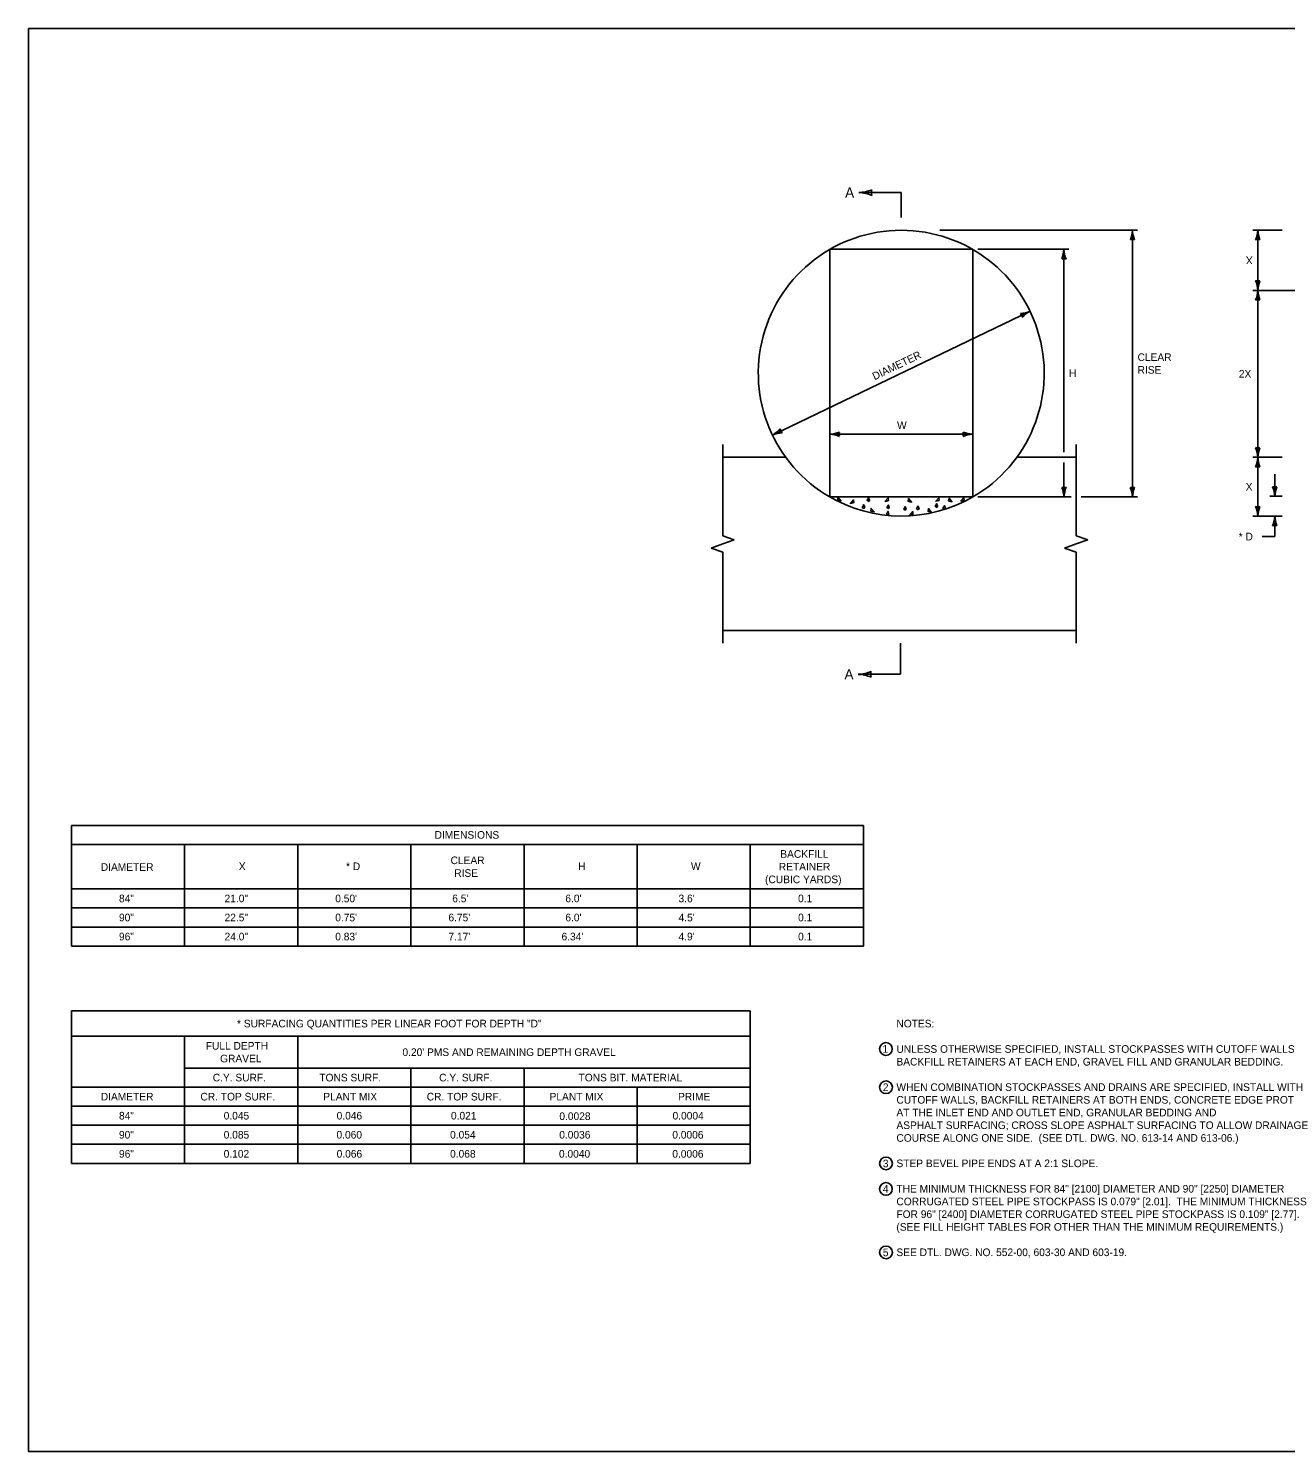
# Model space of a CAD drawing. Extents: x 49991.4 to 50021, y 49987.6 to 50011.4.
# Drawn here: x 49999.38 to 50009.28, y 49987.8 to 49999 of the extents above; entities that cross this region are included whole.
import ezdxf

# ---------------------------------------------------------------- set-up
doc = ezdxf.new("R2010")
doc.units = 0
for name, color, linetype in [('Level 1', 7, 'Continuous'), ('Level 2', 7, 'Continuous'), ('Level 3', 7, 'Continuous'), ('Level 4', 7, 'Continuous'), ('Level 6', 7, 'Continuous')]:
    doc.layers.add(name, color=color, linetype=linetype)

msp = doc.modelspace()

# ---------------------------------------------------------------- linework, layer by layer
at = {"layer": 'Level 1'}
for p, q in [((50004.848, 49995.624), (50005.344, 49995.624)), ((50007.162, 49995.624), (50007.63, 49995.624)), ((50005.691, 49995.312), (50006.816, 49995.312)), ((50004.848, 49994.261), (50007.63, 49994.261))]:
    msp.add_line(p, q, dxfattribs=at)
msp.add_lwpolyline([(49999.384, 49998.999), (50016.75, 49998.999), (50016.75, 49987.799), (49999.384, 49987.799)], close=True, dxfattribs=at)
for points in [[(50005.781, 49995.278), (50005.755, 49995.309), (50005.753, 49995.287), (50005.778, 49995.281)], [(50005.781, 49995.278), (50005.755, 49995.309), (50005.753, 49995.287), (50005.778, 49995.281)], [(50005.851, 49995.258), (50005.877, 49995.288), (50005.879, 49995.267), (50005.853, 49995.26)], [(50005.961, 49995.252), (50005.946, 49995.23), (50005.959, 49995.222), (50005.965, 49995.233), (50005.954, 49995.252)], [(50005.999, 49995.307), (50005.984, 49995.286), (50005.997, 49995.277), (50006.004, 49995.288), (50005.993, 49995.307)], [(50006.124, 49995.275), (50006.15, 49995.305), (50006.152, 49995.283), (50006.126, 49995.277)], [(50006.154, 49995.251), (50006.139, 49995.229), (50006.152, 49995.221), (50006.158, 49995.232), (50006.148, 49995.251)], [(50006.287, 49995.238), (50006.272, 49995.217), (50006.285, 49995.208), (50006.291, 49995.219), (50006.28, 49995.238)], [(50006.335, 49995.269), (50006.309, 49995.299), (50006.307, 49995.278), (50006.332, 49995.271)], [(50006.388, 49995.241), (50006.373, 49995.22), (50006.386, 49995.211), (50006.393, 49995.222), (50006.382, 49995.241)], [(50006.535, 49995.26), (50006.52, 49995.239), (50006.532, 49995.23), (50006.539, 49995.241), (50006.528, 49995.26)], [(50006.523, 49995.276), (50006.549, 49995.306), (50006.551, 49995.285), (50006.526, 49995.278)], [(50006.596, 49995.245), (50006.581, 49995.223), (50006.594, 49995.214), (50006.601, 49995.225), (50006.59, 49995.245)], [(50006.654, 49995.272), (50006.629, 49995.302), (50006.626, 49995.281), (50006.652, 49995.274)], [(50006.719, 49995.278), (50006.745, 49995.308), (50006.747, 49995.287), (50006.721, 49995.28)], [(50006.042, 49995.192), (50006.016, 49995.222), (50006.014, 49995.2), (50006.04, 49995.194)], [(50006.152, 49995.199), (50006.137, 49995.177), (50006.15, 49995.168), (50006.156, 49995.179), (50006.146, 49995.199)], [(50006.317, 49995.167), (50006.343, 49995.197), (50006.345, 49995.176), (50006.32, 49995.169)], [(50006.492, 49995.19), (50006.467, 49995.22), (50006.464, 49995.198), (50006.49, 49995.192)]]:
    msp.add_lwpolyline(points, dxfattribs=at)
for start, end in [(299.9973, 240.0046), (239.1121, 300.3985), (239.1121, 300.3985)]:
    msp.add_arc((50006.253, 49996.286), 1.125, start, end, dxfattribs=at)
at = {"layer": 'Level 2'}
for p, q in [((49999.721, 49992.727), (49999.721, 49991.777)), ((49999.721, 49992.727), (50005.956, 49992.727)), ((50005.956, 49992.727), (50005.956, 49991.777)), ((49999.721, 49992.577), (50005.956, 49992.577)), ((50000.612, 49992.577), (50000.612, 49991.777)), ((50001.503, 49992.577), (50001.503, 49991.777)), ((50002.393, 49992.577), (50002.393, 49991.777)), ((50003.284, 49992.577), (50003.284, 49991.777)), ((50004.175, 49992.577), (50004.175, 49991.777)), ((50005.065, 49992.577), (50005.065, 49991.777)), ((49999.721, 49992.227), (50005.956, 49992.227)), ((49999.721, 49992.077), (50005.956, 49992.077)), ((49999.721, 49991.927), (50005.956, 49991.927)), ((49999.721, 49991.777), (50005.956, 49991.777)), ((49999.721, 49991.267), (49999.721, 49990.067)), ((49999.721, 49991.267), (50005.065, 49991.267)), ((50005.065, 49991.267), (50005.065, 49990.067)), ((49999.721, 49991.067), (50005.065, 49991.067)), ((50000.612, 49991.067), (50000.612, 49990.067)), ((50001.503, 49991.067), (50001.503, 49990.067)), ((50000.612, 49990.817), (50005.065, 49990.817)), ((50002.393, 49990.817), (50002.393, 49990.067)), ((50003.284, 49990.817), (50003.284, 49990.067)), ((49999.719, 49990.667), (50005.065, 49990.667)), ((50004.175, 49990.667), (50004.175, 49990.067)), ((49999.721, 49990.517), (50005.065, 49990.517)), ((49999.721, 49990.367), (50005.065, 49990.367)), ((50003.284, 49990.382), (50003.284, 49990.167)), ((49999.721, 49990.217), (50005.065, 49990.217)), ((49999.721, 49990.067), (50005.065, 49990.067))]:
    msp.add_line(p, q, dxfattribs=at)
for centre in [(50006.132, 49990.967), (50006.133, 49990.666), (50006.133, 49990.066), (50006.132, 49989.866), (50006.133, 49989.366)]:
    msp.add_circle(centre, 0.05, dxfattribs=at)
at = {"layer": 'Level 3'}
for p, q in [((50008.113, 49997.411), (50006.556, 49997.411)), ((50008.073, 49997.411), (50008.073, 49995.312)), ((50009.251, 49997.411), (50009.019, 49997.411)), ((50009.059, 49997.411), (50009.059, 49996.938)), ((50006.856, 49997.261), (50007.573, 49997.261)), ((50007.533, 49997.261), (50007.533, 49995.664)), ((50010.527, 49996.938), (50009.019, 49996.938)), ((50009.059, 49996.938), (50009.059, 49995.624)), ((50005.239, 49995.799), (50007.267, 49996.773)), ((50005.691, 49995.806), (50006.816, 49995.806)), ((50007.533, 49995.312), (50007.533, 49995.584)), ((50009.251, 49995.624), (50009.019, 49995.624)), ((50009.059, 49995.624), (50009.059, 49995.161)), ((50009.193, 49995.49), (50009.193, 49995.317)), ((50006.856, 49995.312), (50007.59, 49995.312)), ((50007.67, 49995.312), (50008.113, 49995.312)), ((50009.153, 49995.317), (50009.251, 49995.317)), ((50009.251, 49995.161), (50009.019, 49995.161)), ((50009.193, 49995.161), (50009.193, 49995)), ((50009.094, 49995), (50009.193, 49995))]:
    msp.add_line(p, q, dxfattribs=at)
for centre, radius, start, end in [((50005.904, 49998.018), 0.311, 272.8273, 292.0772), ((50005.907, 49997.412), 0.296, 67.456, 87.6395), ((50006.09, 49997.708), 0.073, 162.1388, 197.8612), ((50007.851, 49997.42), 0.222, 337.456, 357.6395), ((50008.305, 49997.423), 0.233, 182.8273, 202.0772), ((50008.837, 49997.42), 0.222, 337.456, 357.6395), ((50009.292, 49997.423), 0.233, 182.8273, 202.0772), ((50007.311, 49997.27), 0.222, 337.456, 357.6395), ((50007.766, 49997.272), 0.233, 182.8273, 202.0772), ((50008.073, 49997.283), 0.0548, 72.1388, 107.8612), ((50009.059, 49997.283), 0.0548, 72.1388, 107.8612), ((50007.533, 49997.132), 0.0548, 72.1388, 107.8612), ((50009.059, 49997.066), 0.0548, 252.1388, 287.8612), ((50008.826, 49996.927), 0.233, 2.8273, 22.0772), ((50008.837, 49996.947), 0.222, 337.456, 357.6395), ((50009.281, 49996.929), 0.222, 157.456, 177.6395), ((50009.292, 49996.95), 0.233, 182.8273, 202.0772), ((50009.059, 49996.81), 0.0548, 72.1388, 107.8612), ((50007.179, 49996.978), 0.222, 273.1134, 293.2969), ((50007.152, 49996.718), 0.0548, 7.7962, 43.5185), ((50007.378, 49996.569), 0.233, 118.4847, 137.7345), ((50005.128, 49996.004), 0.233, 298.4847, 317.7345), ((50005.327, 49995.595), 0.222, 93.1134, 113.2969), ((50005.355, 49995.855), 0.0548, 187.7962, 223.5185), ((50005.679, 49996.038), 0.233, 272.8273, 292.0772), ((50005.682, 49995.583), 0.222, 67.456, 87.6395), ((50005.819, 49995.806), 0.0548, 162.1388, 197.8612), ((50006.825, 49996.028), 0.222, 247.456, 267.6395), ((50006.687, 49995.806), 0.0548, 342.1388, 17.8612), ((50006.827, 49995.573), 0.233, 92.8273, 112.0772), ((50009.059, 49995.752), 0.0548, 252.1388, 287.8612), ((50008.826, 49995.612), 0.233, 2.8273, 22.0772), ((50009.281, 49995.614), 0.222, 157.456, 177.6395), ((50008.837, 49995.633), 0.222, 337.456, 357.6395), ((50009.292, 49995.635), 0.233, 182.8273, 202.0772), ((50009.059, 49995.495), 0.0548, 72.1388, 107.8612), ((50007.533, 49995.44), 0.0548, 252.1388, 287.8612), ((50007.301, 49995.3), 0.233, 2.8273, 22.0772), ((50007.756, 49995.303), 0.222, 157.456, 177.6395), ((50008.073, 49995.44), 0.0548, 252.1388, 287.8612), ((50007.84, 49995.3), 0.233, 2.8273, 22.0772), ((50008.295, 49995.303), 0.222, 157.456, 177.6395), ((50009.193, 49995.445), 0.0548, 252.1388, 287.8612), ((50008.96, 49995.305), 0.233, 2.8273, 22.0772), ((50009.415, 49995.307), 0.222, 157.456, 177.6395), ((50009.059, 49995.289), 0.0548, 252.1388, 287.8612), ((50008.826, 49995.15), 0.233, 2.8273, 22.0772), ((50009.281, 49995.152), 0.222, 157.456, 177.6395), ((50008.971, 49995.17), 0.222, 337.456, 357.6395), ((50009.426, 49995.173), 0.233, 182.8273, 202.0772), ((50009.193, 49995.033), 0.0548, 72.1388, 107.8612), ((50005.899, 49994.226), 0.311, 272.8273, 292.0772), ((50005.902, 49993.62), 0.296, 67.456, 87.6395), ((50006.085, 49993.916), 0.073, 162.1388, 197.8612)]:
    msp.add_arc(centre, radius, start, end, dxfattribs=at)
at = {"layer": 'Level 4'}
for p, q in [((50005.691, 49995.312), (50005.691, 49997.261)), ((50005.691, 49997.261), (50006.816, 49997.261)), ((50006.816, 49995.312), (50006.816, 49997.261))]:
    msp.add_line(p, q, dxfattribs=at)
at = {"layer": 'Level 6'}
for p, q in [((50006.253, 49997.708), (50005.92, 49997.708)), ((50006.253, 49997.708), (50006.253, 49997.511)), ((50004.848, 49995.724), (50004.848, 49995.007)), ((50007.63, 49995.724), (50007.63, 49995.007)), ((50004.939, 49994.975), (50004.848, 49995.007)), ((50007.722, 49994.975), (50007.63, 49995.007)), ((50004.848, 49994.942), (50004.757, 49994.91)), ((50004.848, 49994.878), (50004.757, 49994.91)), ((50004.939, 49994.975), (50004.848, 49994.942)), ((50007.63, 49994.942), (50007.539, 49994.91)), ((50007.63, 49994.878), (50007.539, 49994.91)), ((50007.722, 49994.975), (50007.63, 49994.942)), ((50004.848, 49994.878), (50004.848, 49994.161)), ((50007.63, 49994.878), (50007.63, 49994.161)), ((50006.248, 49994.161), (50006.248, 49993.916)), ((50006.248, 49993.916), (50005.914, 49993.916))]:
    msp.add_line(p, q, dxfattribs=at)

# ---------------------------------------------------------------- texts
at = {"layer": 'Level 2'}
for s, height, p in [('A', 0.08, (50005.811, 49997.668)), ('CLEAR', 0.06, (50008.113, 49996.382)), ('H', 0.06, (50007.573, 49996.256)), ('RISE', 0.06, (50008.113, 49996.282)), ('2X', 0.06, (50008.91, 49996.251)), ('W', 0.06, (50006.22, 49995.846)), ('X', 0.06, (50008.964, 49995.362)), ('* D', 0.06, (50008.909, 49994.97)), ('A', 0.08, (50005.806, 49993.876)), ('DIMENSIONS', 0.06, (50002.58, 49992.622)), ('DIAMETER', 0.06, (49999.953, 49992.369)), ('X', 0.06, (50001.039, 49992.375)), ('* D', 0.06, (50001.883, 49992.375)), ('CLEAR', 0.06, (50002.706, 49992.422)), ('H', 0.06, (50003.71, 49992.375)), ('W', 0.06, (50004.598, 49992.375)), ('RETAINER', 0.06, (50005.289, 49992.372)), ('BACKFILL', 0.06, (50005.301, 49992.472)), ('RISE', 0.06, (50002.735, 49992.322)), ('(CUBIC YARDS)', 0.06, (50005.181, 49992.272)), ('84"', 0.06, (50000.096, 49992.122)), ('21.0"', 0.06, (50000.927, 49992.122)), ("0.50'", 0.06, (50001.798, 49992.122)), ("6.5'", 0.06, (50002.719, 49992.122)), ("6.0'", 0.06, (50003.609, 49992.122)), ("3.6'", 0.06, (50004.5, 49992.122)), ('0.1', 0.06, (50005.441, 49992.122)), ('90"', 0.06, (50000.096, 49991.972)), ('22.5"', 0.06, (50000.927, 49991.972)), ("0.75'", 0.06, (50001.798, 49991.972)), ("6.75'", 0.06, (50002.689, 49991.972)), ("6.0'", 0.06, (50003.609, 49991.972)), ("4.5'", 0.06, (50004.5, 49991.972)), ('0.1', 0.06, (50005.441, 49991.972)), ('96"', 0.06, (50000.096, 49991.822)), ('24.0"', 0.06, (50000.927, 49991.822)), ("0.83'", 0.06, (50001.798, 49991.822)), ("7.17'", 0.06, (50002.689, 49991.822)), ("6.34'", 0.06, (50003.579, 49991.822)), ("4.9'", 0.06, (50004.5, 49991.822)), ('0.1', 0.06, (50005.441, 49991.822)), ('* SURFACING QUANTITIES PER LINEAR FOOT FOR DEPTH "D"', 0.06, (50001.025, 49991.137)), ('NOTES:', 0.06, (50006.215, 49991.137)), ('FULL DEPTH', 0.06, (50000.779, 49990.962)), ("0.20' PMS AND REMAINING DEPTH GRAVEL", 0.06, (50002.327, 49990.912)), ('1', 0.06, (50006.105, 49990.938)), ('UNLESS OTHERWISE SPECIFIED, INSTALL STOCKPASSES WITH CUTOFF WALLS AND', 0.06, (50006.215, 49990.937)), ('GRAVEL', 0.06, (50000.892, 49990.862)), ('BACKFILL RETAINERS AT EACH END, GRAVEL FILL AND GRANULAR BEDDING.', 0.06, (50006.215, 49990.837)), ('C.Y. SURF.', 0.06, (50000.834, 49990.712)), ('TONS SURF.', 0.06, (50001.673, 49990.712)), ('C.Y. SURF.', 0.06, (50002.616, 49990.712)), ('TONS BIT. MATERIAL', 0.06, (50003.713, 49990.712)), ('2', 0.06, (50006.108, 49990.636)), ('WHEN COMBINATION STOCKPASSES AND DRAINS ARE SPECIFIED, INSTALL WITH ', 0.06, (50006.215, 49990.637)), ('DIAMETER', 0.06, (49999.953, 49990.562)), ('CR. TOP SURF.', 0.06, (50000.737, 49990.562)), ('PLANT MIX', 0.06, (50001.704, 49990.562)), ('CR. TOP SURF.', 0.06, (50002.518, 49990.562)), ('PLANT MIX', 0.06, (50003.485, 49990.562)), ('PRIME', 0.06, (50004.496, 49990.562)), ('CUTOFF WALLS, BACKFILL RETAINERS AT BOTH ENDS, CONCRETE EDGE PROTECTION', 0.06, (50006.215, 49990.537)), ('84"', 0.06, (50000.096, 49990.412)), ('0.045', 0.06, (50000.92, 49990.412)), ('0.046', 0.06, (50001.809, 49990.412)), ('0.021', 0.06, (50002.709, 49990.412)), ('0.0028', 0.06, (50003.562, 49990.408)), ('0.0004', 0.06, (50004.453, 49990.412)), ('AT THE INLET END AND OUTLET END, GRANULAR BEDDING AND', 0.06, (50006.215, 49990.437)), ('90"', 0.06, (50000.096, 49990.262)), ('0.085', 0.06, (50000.92, 49990.262)), ('0.060', 0.06, (50001.808, 49990.262)), ('0.054', 0.06, (50002.702, 49990.262)), ('0.0036', 0.06, (50003.561, 49990.262)), ('0.0006', 0.06, (50004.451, 49990.262)), ('ASPHALT SURFACING; CROSS SLOPE ASPHALT SURFACING TO ALLOW DRAINAGE', 0.06, (50006.215, 49990.337)), ('COURSE ALONG ONE SIDE.  (SEE DTL. DWG. NO. 613-14 AND 613-06.)', 0.06, (50006.215, 49990.237)), ('96"', 0.06, (50000.096, 49990.112)), ('0.102', 0.06, (50000.92, 49990.112)), ('0.066', 0.06, (50001.809, 49990.112)), ('0.068', 0.06, (50002.702, 49990.112)), ('0.0040', 0.06, (50003.559, 49990.112)), ('0.0006', 0.06, (50004.451, 49990.112)), ('3', 0.06, (50006.108, 49990.036)), ('STEP BEVEL PIPE ENDS AT A 2:1 SLOPE.', 0.06, (50006.215, 49990.037)), ('4', 0.06, (50006.108, 49989.836)), ('THE MINIMUM THICKNESS FOR 84" [2100] DIAMETER AND 90" [2250] DIAMETER', 0.06, (50006.215, 49989.837)), ('CORRUGATED STEEL PIPE STOCKPASS IS 0.079" [2.01].  THE MINIMUM THICKNESS', 0.06, (50006.215, 49989.737)), ('FOR 96" [2400] DIAMETER CORRUGATED STEEL PIPE STOCKPASS IS 0.109" [2.77].', 0.06, (50006.215, 49989.637)), ('(SEE FILL HEIGHT TABLES FOR OTHER THAN THE MINIMUM REQUIREMENTS.)', 0.06, (50006.215, 49989.537)), ('5', 0.06, (50006.108, 49989.336)), ('SEE DTL. DWG. NO. 552-00, 603-30 AND 603-19.', 0.06, (50006.215, 49989.337))]:
    msp.add_text(s, height=height, dxfattribs=at).set_placement(p)
for s, rotation, p in [('X', 180, (50009.019, 49997.205)), ('DIAMETER', 25.6612, (50006.043, 49996.23))]:
    msp.add_text(s, height=0.06, rotation=rotation, dxfattribs=at).set_placement(p)

doc.saveas('drawing.dxf')
